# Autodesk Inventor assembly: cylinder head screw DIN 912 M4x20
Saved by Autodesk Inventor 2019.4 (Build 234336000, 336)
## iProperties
Created: 2021-08
Part Number: cylinder head screw DIN 912 M4x20
Document SubType Name: Assembly
Designer: Administrator
Title: cylinder head screw DIN 912 M4x20 v4
Author: Administrator
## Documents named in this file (2)
- c:\worker\convert-fusion-r06\tmp\job-1\20\output\files\f01db8e3-9ba6-469c-91a4-18b8ab1b818d\cylinder head screw DIN 912 M4x20 v4_1.iam
- c:\worker\convert-fusion-r06\tmp\job-1\20\output\files\f01db8e3-9ba6-469c-91a4-18b8ab1b818d\HI_WUERTH 00824  20 cylinder head screw DIN 912 M4x20 8.8 BLK.ipt
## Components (1 placed, 1 different names)
1. HI_WUERTH 00824  20 cylinder head screw DIN 912 M4x20 8.8 BLK:1
